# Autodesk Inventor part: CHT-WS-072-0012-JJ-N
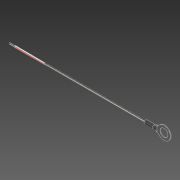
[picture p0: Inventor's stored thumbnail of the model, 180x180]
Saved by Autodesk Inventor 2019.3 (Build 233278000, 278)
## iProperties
Created: 2017-05
Part Number: CHT-WS-072-0012-JJ-N
Material: Generic
Document SubType Name: Modeling
Designer: JN
Density: 1 g/cm^3
Appearance: Steel - Polished
Author: JN
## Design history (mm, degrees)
sketch "Sketch1"
  geometry: L1 (-6.161, 7.121)-(-10.033, 3.563); L2 (-10.033, 3.563)-(-10.033, -3.628); L3 (-10.033, -3.628)-(-6.161, -7.186); L4 (-10.033, -0.032)-(10.129, -0.032); L5 (4.711, 8.681)-(4.711, -8.745); C1 r 6.001 at (0.413, -0.032); A1 r 9.716 centre (0.413, -0.032) between (-6.161, -7.186) and (-6.161, 7.121)
  constraints: 10 end point, 5 point on circle, 2 centre point, 2 tangent, 2 vertical, 1 coincident, 1 midpoint, 1 other
  dimensions: "d0" = 12.0015 diameter of C1; "d1" = 19.431 diameter of A1; "d66" = 4.445 distance edge to line of C1 L2
extrude "Extrusion1" new body sketch "Sketch1" stored distance "d7" = 1.0668; taper "d8" = 0 deg
sketch "Sketch3"
  geometry: L1 (0, 0)-(-1.067, 0) reference; L2 (0, 7.191)-(0, 0) reference; L3 (0, 7.191)-(-1.067, 7.191) reference; L4 (-1.067, 0)-(-1.067, 7.191) reference; L5 (0.317, 7.508)-(-1.702, 7.508); L6 (-1.702, 7.508)-(-1.702, -0.318); L7 (-1.702, -0.318)-(0.317, -0.318); L8 (0.317, -0.318)-(0.317, 7.508); L9 (-0.692, 7.508)-(-0.692, -0.318); L10 (0.317, 3.595)-(-1.702, 3.595); 1 further point
  constraints: 12 end point, 6 parallel, 5 midpoint, 1 horizontal, 1 perpendicular
  dimensions: "d15" = 0.3175 distance between parallel lines of L2 L8; "d16" = 0.635 distance between parallel lines of L4 L6; "d17" = 0.3175 distance between parallel lines of L3 L5; "d18" = 0.3175 distance between parallel lines of L1 L7
  node "Projected Loop1"
workplane "Work Plane1"
sketch "Sketch4"
  geometry: L1 (0.317, -0.318)-(0.317, 7.508) reference; L2 (0.317, 7.508)-(-1.702, 7.508) reference; L3 (-1.702, 7.508)-(-1.702, -0.318) reference; L4 (-1.702, -0.318)-(0.317, -0.318) reference; L5 (0.317, 3.595)-(-1.702, 3.595); L6 (-0.692, 7.508)-(-0.692, -0.318); L7 (-2.337, 5.531)-(-2.337, 1.66); A1 r 2.54 centre (-0.692, 3.595) between (-2.337, 1.66) and (-2.337, 5.531); 2 further points
  constraints: 6 end point, 5 midpoint, 2 point on circle, 1 centre point, 1 coincident, 1 point on line, 1 vertical
  dimensions: "d37" = 5.08 diameter of A1; "d38" = 0.635 distance between parallel lines of L3 L7
sketch "3D Sketch1"
loft "Loft1" sketch "Sketch4", "3D Sketch1" dims "d21" = 0, "d22" = 90 deg, "d25" = 0, "d26" = 90 deg, "d39" = 0, "d40" = 90 deg
sketch "Sketch5"
  geometry: L1 (-1.645, 1.936)-(-1.645, -1.936) reference; A1 r 2.54 centre (0, 0) between (0.038, -2.54) and (0.843, 2.396) reference; A2 r 2.54 centre (0, 0) between (0.843, 2.396) and (-1.645, 1.936) reference; A3 r 2.54 centre (0, 0) between (0.843, 2.396) and (-1.645, 1.936) reference; A4 r 2.54 centre (0, 0) between (-1.645, -1.936) and (0.038, -2.54) reference; A5 r 2.54 centre (0, 0) between (0.038, -2.54) and (0.843, 2.396) reference
extrude "Extrusion3" new body sketch "Sketch5" distance "d27" = 12.7; taper "d28" = 0 deg
sketch "Sketch6" dims "d29" = 1.27, "d30" = 1.778
  geometry: L1 (0, 3.446)-(2.019, 3.446); L2 (2.54, 0)-(-1.645, 0); L3 (-1.645, 1.936)-(-1.645, -1.936) reference; A1 r 2.54 centre (0, 0) between (0.038, -2.54) and (0.843, 2.396) reference; 2 further points; 1 other entity
  constraints: 4 end point, 2 midpoint, 1 point on circle, 2 other
extrude "Extrusion4" cut sketch "Sketch6" stored distance "d32" = 12.7; taper "d33" = 0 deg
extrude "Extrusion5" new body sketch "Sketch6" distance "d34" = 152.4; taper "d35" = 0 deg
workplane "Work Plane2"
sketch "Sketch8"
  geometry: C1 r 0.635 at (0.187, 0.635) reference; C2 r 0.635 at (0.187, -0.635) reference; C3 r 0.635 at (0.187, 0.952); C4 r 0.635 at (0.187, -0.953)
  constraints: 2 centre point
  dimensions: "d43" = 1.27 diameter of C3; "d45" = 0.3175 distance of C1.centre C3.centre; "d46" = 1.27 diameter of C4; "d47" = 0.3175 distance of C2.centre C4.centre
sketch "3D Sketch2"
loft "Loft2" dims "d48" = 0, "d49" = 90 deg, "d50" = 0, "d51" = 90 deg, "d52" = 0, "d53" = 90 deg
loft "Loft3" dims "d54" = 0, "d55" = 90 deg, "d56" = 0, "d57" = 90 deg, "d58" = 0, "d59" = 90 deg
sketch "Sketch9"
  geometry: C1 r 0.381 at (0, 0)
  constraints: 1 centre point
  dimensions: "d60" = 0.762 diameter of C1
sketch "Sketch10"
  geometry: C1 r 0.381 at (0, 0)
  constraints: 1 centre point
  dimensions: "d61" = 0.762 diameter of C1
extrude "Extrusion6" join sketch "Sketch9" distance "d62" = 8.46667; taper "d63" = 0 deg
extrude "Extrusion7" join sketch "Sketch10" distance "d64" = 8.46667; taper "d65" = 0 deg
body "Solid1"
sketch "Sketch7"
  geometry: L1 (1.01, 1.395)-(1.01, -1.395) reference; L2 (-1.048, 0)-(1.492, 0); C1 r 0.635 at (0.187, 0.635); C2 r 0.635 at (0.187, -0.635); 3 further points; 3 other entities
  constraints: 4 end point, 2 centre point, 2 tangent, 2 vertical, 1 horizontal, 8 other
  dimensions: "d41" = 1.27 diameter of C1
body "Solid2"
body "Solid3"
body "Solid4"
node "Projected Loop5"
other parameters: "d3" = 14.986 (derived), "d5" = 10.49782 (derived), "d19" = 5.08, "d42" = 44.45
